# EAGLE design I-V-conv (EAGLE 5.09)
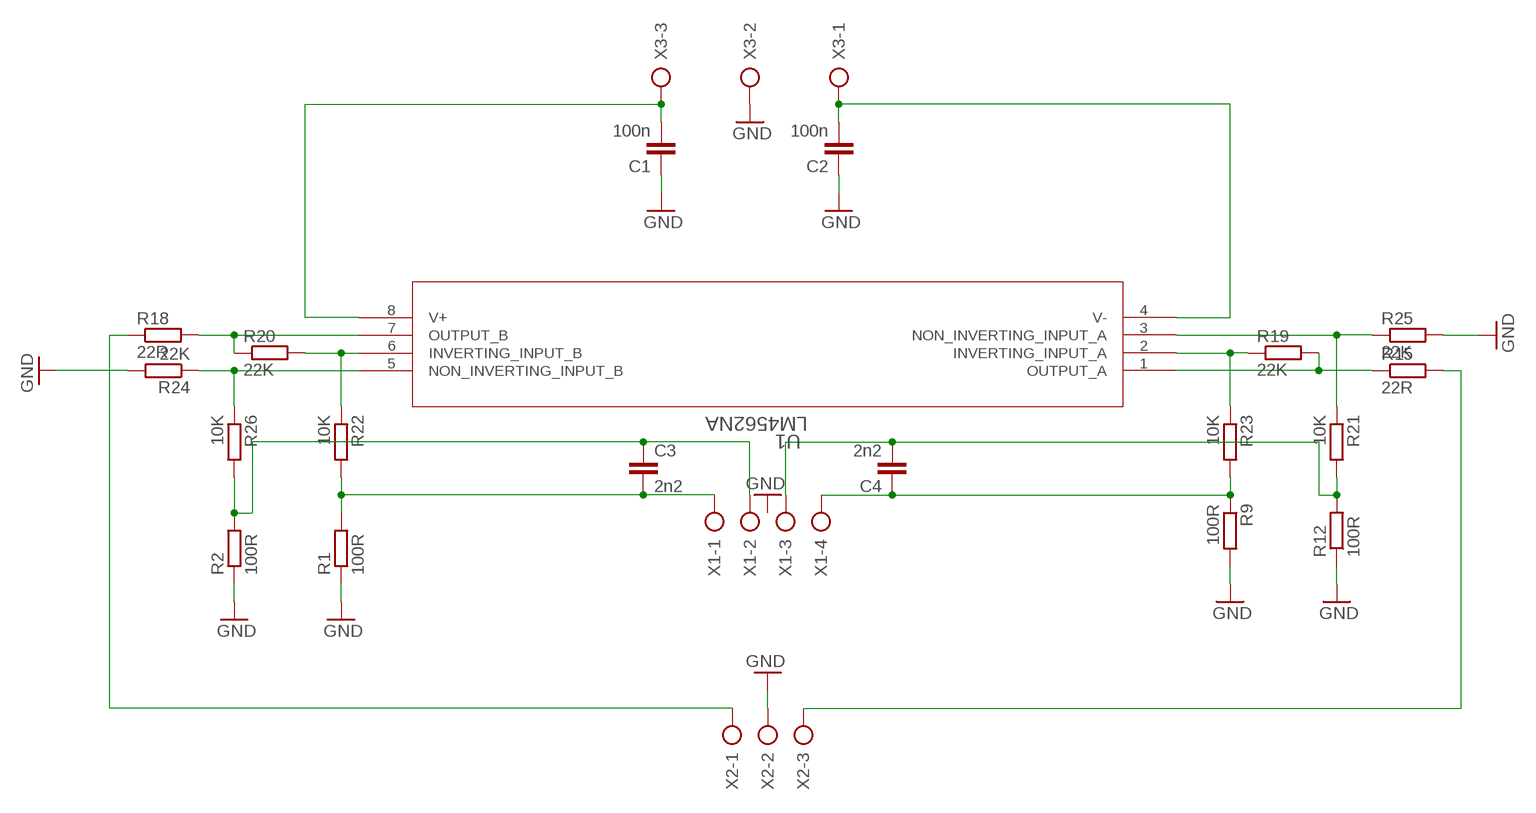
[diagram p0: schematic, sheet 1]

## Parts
C1  100n  C7.5/3  [C7.5B3]
C2  100n  C7.5/3  [C7.5B3]
C3  2n2  C2.5/2  [C2.5-2]
C4  2n2  C2.5/2  [C2.5-2]
R1  100R  R-EU_0207/12  [0207/12]
R2  100R  R-EU_0207/12  [0207/12]
R9  100R  R-EU_0207/12  [0207/12]
R12  100R  R-EU_0207/12  [0207/12]
R15  22R  R-EU_0207/10  [0207/10]
R18  22R  R-EU_0207/10  [0207/10]
R19  22K  R-EU_0207/10  [0207/10]
R20  22K  R-EU_0207/10  [0207/10]
R21  10K  R-EU_0207/10  [0207/10]
R22  10K  R-EU_0207/10  [0207/10]
R23  10K  R-EU_0207/10  [0207/10]
R24  22K  R-EU_0207/10  [0207/10]
R25  22K  R-EU_0207/10  [0207/10]
R26  10K  R-EU_0207/10  [0207/10]
U1  LM4562NA  [N08E]
X1  AK500/4  [AK500/4]
X2  AK500/3  [AK500/3]
X3  AK500/3  [AK500/3]

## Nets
GND: C1.1 C2.1 R1.1 R2.1 R9.2 R12.1 R24.2 R25.2 X2.2 X3.2
N$1: C1.2 U1.8(V+) X3.3
N$2: C2.2 U1.4(V-) X3.1
N$3: R18.1 X2.1
N$4: R15.2 X2.3
N$5: C4.2 R12.2 R21.2 X1.3
N$6: R15.1 R19.2 U1.1(OUTPUT_A)
N$7: C3.2 R1.2 R22.2 X1.1
N$8: R24.1 R26.1 U1.5(NON_INVERTING_INPUT_B)
N$9: C4.1 R9.1 R23.2 X1.4
N$10: C3.1 R2.2 R26.2 X1.2
N$11: R18.2 R20.1 U1.7(OUTPUT_B)
N$12: R21.1 R25.1 U1.3(NON_INVERTING_INPUT_A)
N$13: R19.1 R23.1 U1.2(INVERTING_INPUT_A)
N$15: R20.2 R22.1 U1.6(INVERTING_INPUT_B)

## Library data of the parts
C1-C4 = capacitor-wima:C: CAPACITOR
R1 R2 R9 R12 R15 R18-R26 = resistor:R-EU_: RESISTOR, European symbol
U1 = lm4562NA:LM4562NA; BASE_PN: LM4562; COMPTYPE: AudioIC; PARTNUMBER: LM4562NA; SYMBOL: NameLM4562NA; TYPE: LM4562NA; VENDOR: NationalSemiconductor; VERSION: 05/02/2007
X1 = con-ptr500:AK500/4: CONNECTOR
X2 X3 = con-ptr500:AK500/3: CONNECTOR

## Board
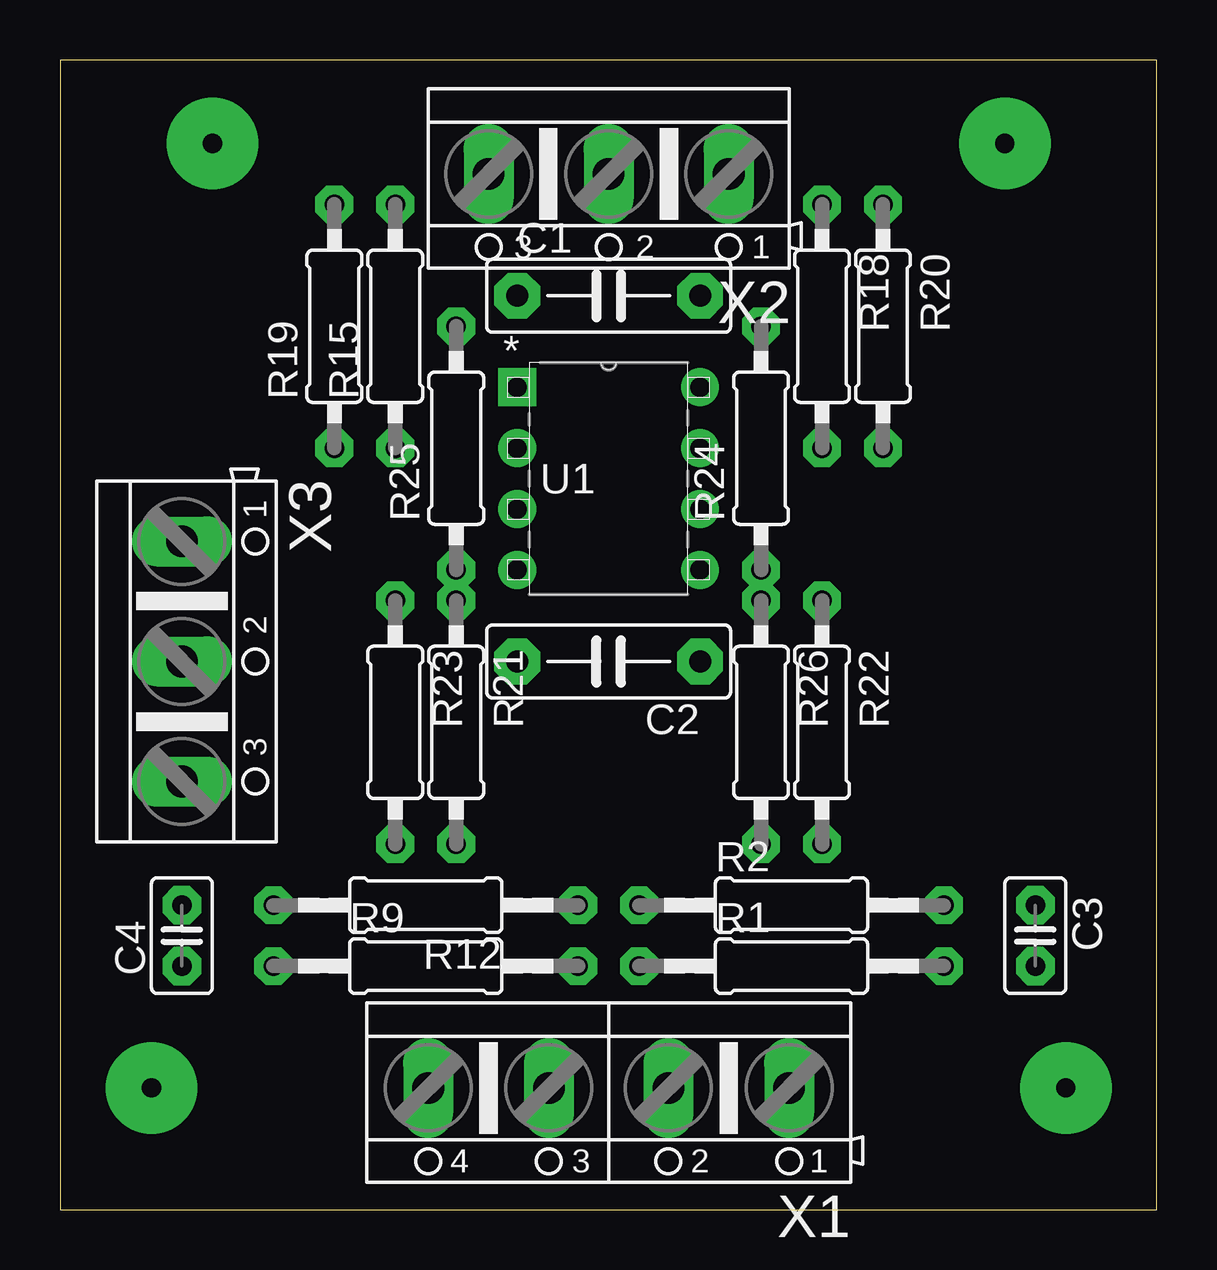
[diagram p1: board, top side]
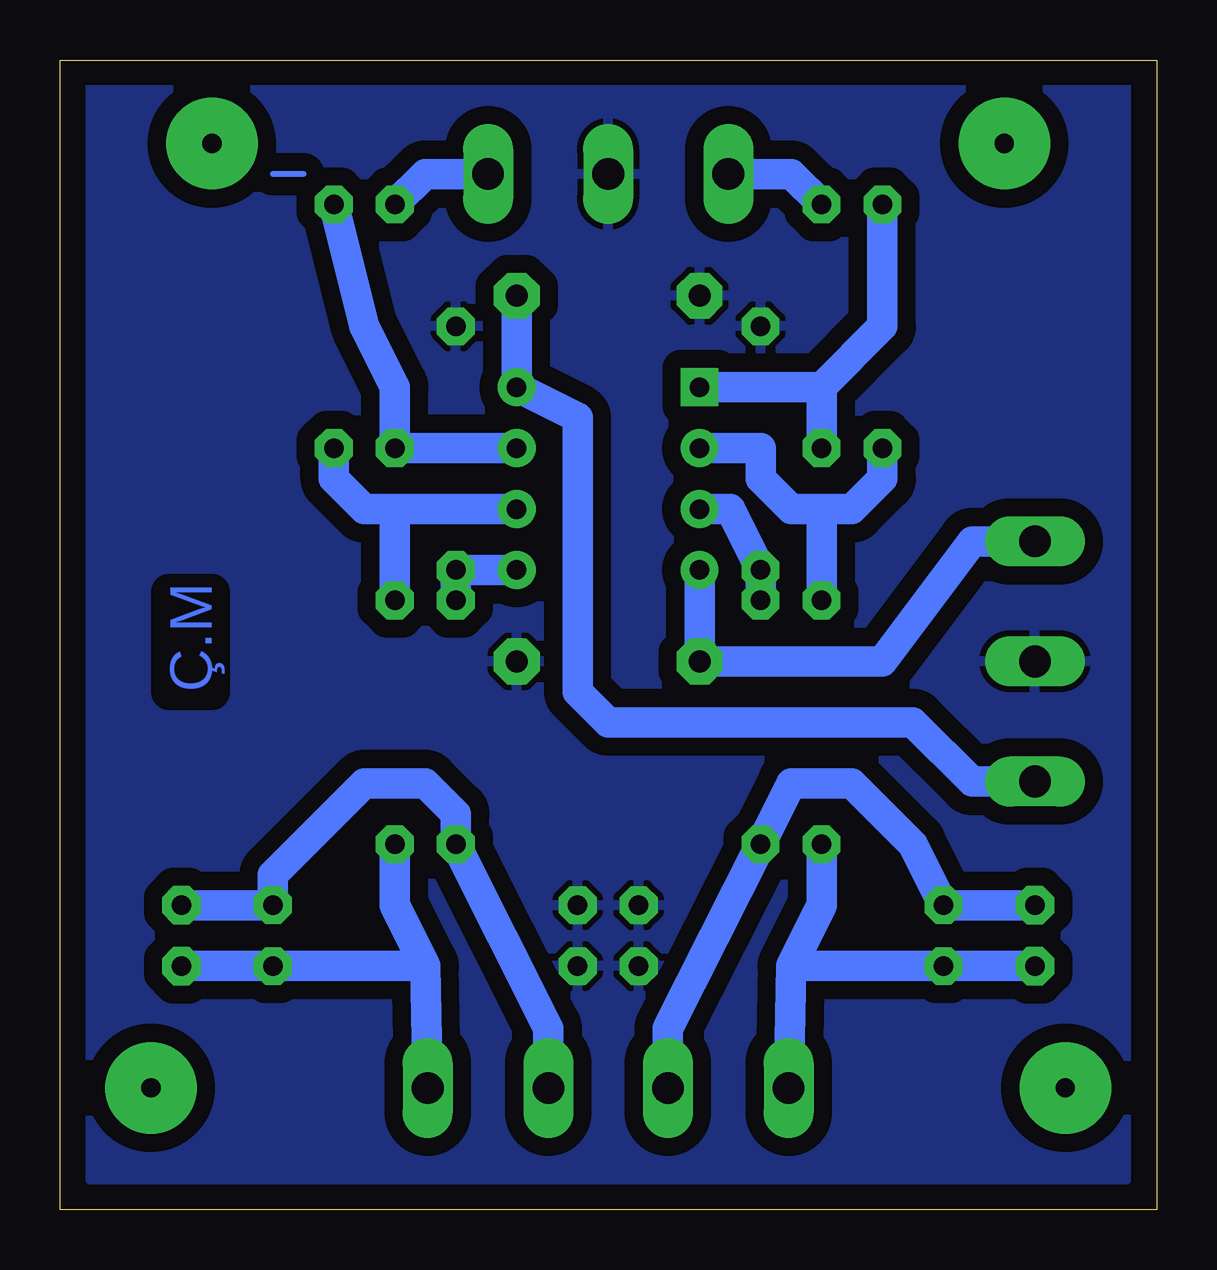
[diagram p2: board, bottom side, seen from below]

Size 45.7 x 47.93 mm. Coordinates in mm from the lower left corner, seen from the top.
Outline: 0,0 45.7,0 45.7,47.93 0,47.93 0,0
Copper layers (1*16): Top 0.035mm / dielectric 1.5mm / Bottom 0.035mm
Design rules "default *": minimum track width 20mil, minimum drill 24mil, track to track 30mil, track to pad 30mil, pad to pad 20mil, via to via 15mil, smd to smd 8mil, copper to edge 40mil, drill to drill 30mil, minimum pad ring 15mil, minimum via ring 20mil, stop-mask expansion 4mil, vias tented up to drill 0mil, thermal gap 10mil

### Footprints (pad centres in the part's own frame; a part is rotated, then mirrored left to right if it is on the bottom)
C7.5B3 = drill 0.914 pad 1.905 octagon: 1 -3.81,0; 2 3.81,0
C2.5-2 = drill 0.813 pad 1.6 octagon: 1 -1.27,0; 2 1.27,0
0207/12 = drill 0.813 octagon: 1 -6.35,0; 2 6.35,0
0207/10 = drill 0.813 octagon: 1 -5.08,0; 2 5.08,0
N08E = drill 0.813 square: 1 -7.62,7.62 | drill 0.813 round: 2 -7.62,5.08; 3 -7.62,2.54; 4 -7.62,0; 5 0,0; 6 0,2.54; 7 0,5.08; 8 0,7.62
AK500/4 = drill 1.321 long: 1 -7.518,0; 2 -2.489,0; 3 2.489,0; 4 7.518,0
AK500/3 = drill 1.321 long: 1 -5.004,0; 2 0,0; 3 5.004,0

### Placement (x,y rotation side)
C1  22.86,38.1 0 top
C2  22.86,22.86 180 top
C3  40.64,11.43 270 top
C4  5.08,11.43 90 top
R1  30.48,10.16 0 top
R2  30.48,12.7 0 top
R9  15.24,10.16 0 top
R12  15.24,12.7 180 top
R15  13.97,36.83 90 top
R18  31.75,36.83 270 top
R19  11.43,36.83 90 top
R20  34.29,36.83 270 top
R21  16.51,20.32 270 top
R22  31.75,20.32 270 top
R23  13.97,20.32 270 top
R24  29.21,31.75 90 top
R25  16.51,31.75 90 top
R26  29.21,20.32 270 top
U1  26.67,26.67 0 top
X1  22.86,5.08 180 top
X2  22.86,43.18 180 top
X3  5.08,22.86 270 top

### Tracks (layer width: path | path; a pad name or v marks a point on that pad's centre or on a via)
GND
  pour Bottom: 1.27,46.99 44.45,46.99 44.45,1.27 1.27,1.27
N$1
  Bottom 1.27: C1.2 U1.8 24.13,33.02 24.13,21.59 22.86,20.32 10.16,20.32 7.7,17.86 X3.3
N$2
  Bottom 1.27: U1.4 C2.2 11.43,22.86 7.7,27.86 X3.1
N$3
  Bottom 1.27: R18.1 30.48,43.18 X2.1
N$4
  Bottom 1.27: R15.2 15.24,43.18 X2.3
N$5
  Bottom 1.27: X1.3 20.37,7.57 R21.2 15.24,17.78 12.7,17.78 10.16,15.24 R12.2 C4.2
N$6
  Bottom 1.27: 13.97,34.29 U1.1 | R15.1 13.97,34.29 | R19.2 11.43,36.83 13.97,34.29
N$7
  Bottom 1.27: X1.1 30.48,10.16 | 30.48,10.16 31.75,12.7 R22.2 | 30.48,10.16 R1.2 C3.2
N$8
  Bottom 1.27: U1.5 R24.1 R26.1
N$9
  Bottom 1.27: 15.24,10.16 X1.4 | 15.24,10.16 13.97,12.7 R23.2 | C4.1 R9.1 15.24,10.16
N$10
  Bottom 1.27: X1.2 25.35,7.57 R26.2 29.21,16.51 30.48,17.78 33.02,17.78 36.83,13.97 R2.2 C3.1
N$11
  Bottom 1.27: U1.7 R18.2 31.75,34.29 33.02,36.83 R20.1
N$12
  Bottom 1.27: R21.1 R25.1 17.78,29.21 U1.3
N$13
  Bottom 1.27: 13.97,29.21 15.24,29.21 16.51,30.48 16.51,31.75 U1.2 | R23.1 13.97,29.21 | R19.1 11.43,30.48 12.7,29.21 13.97,29.21
N$14  (via drill 0.8 pad 3.81)
  other vias: 6.35,44.45
N$15
  Bottom 1.27: 31.75,29.21 U1.6 | R22.1 31.75,29.21 | R20.2 34.29,30.48 33.02,29.21 31.75,29.21
N$16  (via drill 0.8 pad 3.81)
  other vias: 39.37,44.45
N$17  (via drill 0.8 pad 3.81)
  other vias: 3.81,5.08
N$18  (via drill 0.8 pad 3.81)
  other vias: 41.91,5.08
N$19
  Bottom 0.254: 35.56,43.18 36.83,43.18

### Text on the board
Bottom: Ç.M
